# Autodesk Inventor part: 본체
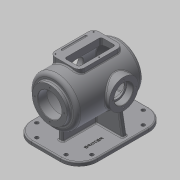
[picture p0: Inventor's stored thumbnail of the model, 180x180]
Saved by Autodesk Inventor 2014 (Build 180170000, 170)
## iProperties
Created: 2016-02
Part Number: 본체
Material: 일반
Document SubType Name: Modeling
Designer: mduedu
Density: 2.71 g/cm^3
Appearance: 기본값
Author: mduedu
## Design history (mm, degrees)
sketch "스케치2"
  geometry: L1 (0, 100)-(0, -100); L2 (65, -75.993)-(65, 100); L3 (65, 100)-(0, 100); A1 r 100 centre (0, 0) between (0, -100) and (65, -75.993); 2 further points
  constraints: 6 end point, 2 midpoint, 2 point on circle, 1 centre point, 1 coincident, 1 horizontal, 1 parallel, 1 vertical
  dimensions: "d3" = 200 distance of L1.start L1.end; "d5" = 130 diameter of L2 L1; "d6" = 100 radius of A1
revolve "회전1" sketch "스케치2" stored, may be unused: angle "d7" = 90 deg
sketch "스케치3"
  geometry: C1 r 47.5 at (0, 0); 1 further point
  constraints: 1 centre point, 1 coincident
  dimensions: "d8" = 95 diameter of C1
extrude "돌출2" join sketch "스케치3" distance "d10" = 10; taper "d11" = 0 deg
sketch "스케치5"
  geometry: L1 (47.5, 110)-(47.5, 100) reference; L2 (47.5, 100)-(65, 100) reference; L3 (65, 100)-(65, -75.993) reference; L4 (-65, -75.993)-(-65, 100) reference; L5 (-65, 100)-(-47.5, 100) reference; L6 (-47.5, 100)-(-47.5, 110) reference; L7 (-47.5, 110)-(47.5, 110) reference; L8 (55, 85)-(55, -71.239); L9 (0, 85)-(55, 85); L10 (0, 85)-(0, -90); A1 r 100 centre (0, 0) between (0, -100) and (65, -75.993) reference; A2 r 100 centre (0, 0) between (-65, -75.993) and (0, -100) reference; A3 r 90 centre (0, 0) between (0, -90) and (55, -71.239); 1 further point
  constraints: 6 end point, 2 point on circle, 1 centre point, 1 parallel, 1 perpendicular, 1 point on line, 1 vertical
  dimensions: "d13" = 10 distance between parallel lines of L3 L8; "d14" = 10 radial gap between concentric circles of A3 A1; "d15" = 15 distance between parallel lines of L9 L2
revolve "회전2" sketch "스케치5" stored, may be unused: angle "d16" = 90 deg
hole "구멍1" diameter "d19" = 65; stored, may be unused: countersink angle "d23" = 90 deg, drill point angle "d25" = 118 deg; dims "d17" = 10, "d18" = 10, "d20" = 6, "d21" = 4, "d22" = 2, "d24" = 8
node "작업 평면1"
sketch "스케치6"
  geometry: L1 (47.5, 110)-(-47.5, 110) reference; C1 r 40 at (0, -17); 1 further point
  constraints: 1 centre point, 1 vertical alignment
  dimensions: "d27" = 80 diameter of C1; "d29" = 127 distance from line of C1.centre L1
extrude "돌출3" join sketch "스케치6" stored distance "d30" = 10; taper "d31" = 0 deg
hole "구멍2" diameter "d34" = 42; stored, may be unused: countersink angle "d38" = 90 deg, drill point angle "d40" = 118 deg; dims "d32" = 10, "d33" = 10, "d35" = 6, "d36" = 52, "d37" = 18, "d39" = 8
sketch "스케치7" dims "d41" = 65
  geometry: C1 r 40 at (0, 0) reference; 3 further points
  constraints: 2 vertical alignment, 1 coincident, 2 other
hole "구멍3" sketch "스케치7" at (0, 32.5) diameter "d43" = 3.242; stored, may be unused: countersink angle "d47" = 90 deg, drill point angle "d49" = 118 deg; dims "d44" = 11, "d45" = 13, "d46" = 18, "d48" = 13
sketch "스케치8" dims "d53" = 80
  geometry: 3 further points
  constraints: 2 vertical alignment, 1 coincident, 2 other
hole "구멍4" sketch "스케치8" at (0, 40) diameter "d56" = 3.242; stored, may be unused: countersink angle "d60" = 90 deg, drill point angle "d62" = 118 deg; dims "d57" = 11, "d58" = 13, "d59" = 18, "d61" = 13
fillet "모깎기1" dims "d66" = 10
fillet "모깎기2" dims "d67" = 3
fillet "모깎기3" dims "d68" = 0.3
chamfer "모따기1" distance "d69" = 1; stored, may be unused: second distance "d70" = 2, angle "d71" = 45 deg
node "작업 평면5"
sketch "스케치23"
  geometry: L1 (6, 80)-(-6, 80); L2 (-6, 80)-(-6, -60); L3 (-6, -60)-(6, -60); L4 (6, -60)-(6, 80); L5 (-55, 100)-(55, 100) reference; 2 further points
  constraints: 8 end point, 2 parallel, 1 horizontal, 1 midpoint, 1 perpendicular, 1 vertical alignment
  dimensions: "d177" = 12 distance of L1.start L1.end; "d179" = 140 distance of L3.end L1.start; "d180" = 20 distance between parallel lines of L1 L5
extrude "돌출14" join sketch "스케치23" stored distance "d181" = 10; taper "d182" = 0 deg
node "작업 평면6"
sketch "스케치15"
  geometry: L1 (-30, 60)-(50, 60); L2 (50, 60)-(50, -60); L3 (50, -60)-(-30, -60); L4 (-30, -60)-(-30, 60); 3 further points
  constraints: 8 end point, 2 parallel, 1 horizontal, 1 horizontal alignment, 1 midpoint, 1 perpendicular, 1 vertical alignment
  dimensions: "d110" = 80 distance of L2.end L3.end; "d112" = 60 distance from line of L3 point (10, 0); "d113" = 120 distance of L1.end L2.end; "d149" = 30 distance from line of L4 point (0, 0)
extrude "돌출8" join sketch "스케치15" stored distance "d114" = 10; taper "d115" = 0 deg
fillet "모깎기7" dims "d116" = 15
sketch "스케치16"
  geometry: L1 (-30, -45)-(-30, 45) reference; L2 (-15, 60)-(35, 60) reference; L3 (35, -60)-(-15, -60) reference; L4 (-20, -45)-(-20, 45); L5 (-15, 50)-(15, 50); L6 (20, 45)-(20, -45); L7 (15, -50)-(-15, -50); L8 (50, 45)-(50, -45) reference; A1 r 15 centre (-15, -45) between (-30, -45) and (-15, -60) reference; A2 r 15 centre (-15, 45) between (-15, 60) and (-30, 45) reference; A3 r 5 centre (-15, -45) between (-20, -45) and (-15, -50); A4 r 5 centre (-15, 45) between (-15, 50) and (-20, 45); A5 r 5 centre (15, 45) between (20, 45) and (15, 50); A6 r 5 centre (15, -45) between (15, -50) and (20, -45); A7 r 15 centre (35, 45) between (50, 45) and (35, 60) reference; A8 r 15 centre (35, -45) between (35, -60) and (50, -45) reference
  constraints: 8 end point, 8 point on circle, 4 centre point, 2 equal radius, 3 other
  dimensions: "d137" = 10 distance between parallel lines of L4 L1; "d150" = 40 distance between parallel lines of L6 L4; "d151" = 100 distance between parallel lines of L7 L5
extrude "돌출9" cut sketch "스케치16" stored distance "d118" = 10; taper "d119" = 0 deg
fillet "모깎기8" dims "d120" = 3
sketch "스케치17"
  geometry: L1 (-30, -45)-(-30, 45) reference; L2 (-20, 45)-(-20, -45) reference; L3 (-15, -50)-(15, -50) reference; L4 (20, -45)-(20, 45) reference; L5 (15, 50)-(-15, 50) reference; L6 (-15, 60)-(35, 60) reference; L7 (35, -60)-(-15, -60) reference; L8 (15, 55)-(-15, 55); L9 (-25, 45)-(-25, -45); L10 (-15, -55)-(15, -55); L11 (25, -45)-(25, 45); L12 (50, 45)-(50, -45) reference; L13 (35, 55)-(-15, 55); L14 (-25, 45)-(-25, -45); L15 (-15, -55)-(35, -55); L16 (45, -45)-(45, 45); A1 r 5 centre (-15, 45) between (-15, 50) and (-20, 45) reference; A2 r 5 centre (-15, -45) between (-20, -45) and (-15, -50) reference; A3 r 5 centre (15, -45) between (15, -50) and (20, -45) reference; A4 r 5 centre (15, 45) between (20, 45) and (15, 50) reference; A5 r 15 centre (-15, 45) between (-15, 60) and (-30, 45) reference; A6 r 15 centre (-15, -45) between (-30, -45) and (-15, -60) reference; A7 r 10 centre (-15, 45) between (-15, 55) and (-25, 45); A8 r 10 centre (-15, -45) between (-25, -45) and (-15, -55); A9 r 10 centre (15, -45) between (15, -55) and (25, -45); A10 r 10 centre (15, 45) between (25, 45) and (15, 55); A11 r 15 centre (35, 45) between (50, 45) and (35, 60) reference; A12 r 15 centre (35, -45) between (35, -60) and (50, -45) reference; A13 r 10 centre (-15, 45) between (-15, 55) and (-25, 45); A14 r 10 centre (-15, -45) between (-25, -45) and (-15, -55); A15 r 10 centre (35, -45) between (35, -55) and (45, -45); A16 r 10 centre (35, 45) between (45, 45) and (35, 55); 6 further points
  constraints: 18 point on circle, 16 end point, 8 centre point, 4 midpoint, 4 tangent, 11 other
  dimensions: "d138" = 5 distance between parallel lines of L8 L6; "d157" = 5 distance between parallel lines of L12 L16
hole "구멍5" sketch "스케치17" at (-25, 0), (42.071, 52.071), (42.071, -52.071) diameter "d122" = 3.242; stored, may be unused: countersink angle "d126" = 90 deg, drill point angle "d128" = 118 deg; dims "d123" = 9, "d124" = 13, "d125" = 18, "d127" = 11
sketch "스케치19"
  geometry: L1 (-50, 70)-(-35, 70) reference; L2 (-50, 42.603)-(-50, 70) reference; C1 r 2.5 at (-43, 70); 1 further point
  constraints: 1 centre point, 1 point on line
  dimensions: "d152" = 5 diameter of C1; "d153" = 7 distance from line of C1.centre L2
extrude "돌출11" cut sketch "스케치19" stored distance "d154" = 70; taper "d155" = 0 deg
fillet "모깎기11" dims "d156" = 2.5
sketch "스케치20"
  geometry: L1 (-90, 120)-(90, 120); L2 (90, 120)-(90, -120); L3 (90, -120)-(-90, -120); L4 (-90, -120)-(-90, 120); 3 further points
  constraints: 8 end point, 2 parallel, 2 vertical alignment, 1 coincident, 1 horizontal, 1 midpoint, 1 perpendicular
  dimensions: "d162" = 180 distance of L1.start L1.end; "d164" = 240 distance of L1.end L2.end; "d165" = 120 distance from line of L1 point (0, 0)
extrude "돌출12" join sketch "스케치20" distance "d166" = 10; taper "d167" = 0 deg
fillet "모깎기12" dims "d168" = 50
node "작업 평면8"
  node "작업축1"
sketch "스케치24"
  geometry: L1 (128, 34.121)-(127.026, 32.5) reference; L2 (127.026, 32.5)-(128, 30.879) reference; L3 (128, 30.879)-(141, 30.879) reference; L4 (141, 30.879)-(141, 27) reference; L5 (141, 27)-(140, 26) reference; L6 (140, 26)-(123.3, 26) reference; L7 (123, 25.7)-(123, 21) reference; L8 (123, 21)-(116.833, 21) reference; L9 (86, 51.235)-(86, 70) reference; L10 (86, 70)-(106.5, 70) reference; L11 (111.5, 70)-(116, 70) reference; L12 (116, 70)-(116, 42.603) reference; L13 (118.678, 40)-(141, 40) reference; L14 (141, 40)-(141, 34.121) reference; L15 (141, 34.121)-(128, 34.121) reference; L16 (4, -34.121)-(4.974, -32.5) reference; L17 (4.974, -32.5)-(4, -30.879) reference; L18 (4, -30.879)-(-9, -30.879) reference; L19 (-9, -30.879)-(-9, -27) reference; L20 (-9, -27)-(-8, -26) reference; L21 (-8, -26)-(8.7, -26) reference; L22 (9, -25.7)-(9, -21) reference; L23 (9, -21)-(15.167, -21) reference; L24 (116.833, -21)-(123, -21) reference; L25 (123, -21)-(123, -25.7) reference; L26 (123.3, -26)-(140, -26) reference; L27 (140, -26)-(141, -27) reference; L28 (141, -27)-(141, -30.879) reference; L29 (141, -30.879)-(128, -30.879) reference; L30 (128, -30.879)-(127.026, -32.5) reference; L31 (127.026, -32.5)-(128, -34.121) reference; L32 (128, -34.121)-(141, -34.121) reference; L33 (141, -34.121)-(141, -40) reference; L34 (141, -40)-(118.678, -40) reference; L35 (72, -64.722)-(72, -100) reference; L36 (72, -100)-(156, -100) reference; L37 (156, -100)-(156, -110) reference; L38 (156, -110)-(-24, -110) reference; L39 (-24, -110)-(-24, -100) reference; L40 (-24, -100)-(60, -100) reference; L41 (60, -100)-(60, -64.722) reference; L42 (13.322, -40)-(-9, -40) reference; L43 (-9, -40)-(-9, -34.121) reference; L44 (-9, -34.121)-(4, -34.121) reference; L45 (4.974, 32.5)-(4, 34.121) reference; L46 (4, 34.121)-(-9, 34.121) reference; L47 (-9, 34.121)-(-9, 40) reference; L48 (-9, 40)-(13.322, 40) reference; L49 (36, 59.456)-(36, 70) reference; L50 (36, 70)-(46, 70) reference; L51 (46, 70)-(46, 51.235) reference; L52 (15.167, 21)-(9, 21) reference; L53 (9, 21)-(9, 25.7) reference; L54 (8.7, 26)-(-8, 26) reference; L55 (-8, 26)-(-9, 27) reference; L56 (-9, 27)-(-9, 30.879) reference; L57 (-9, 30.879)-(4, 30.879) reference; L58 (4, 30.879)-(4.974, 32.5) reference; L59 (-1, -40)-(-11.58, -100); A1 r 0.3 centre (123.3, 25.7) between (123.3, 26) and (123, 25.7) reference; A2 r 55 centre (66, 0) between (116.833, 21) and (86, 51.235) reference; A3 r 2.5 centre (109, 70) between (106.5, 70) and (111.5, 70) reference; A4 r 3 centre (119, 42.603) between (116, 42.603) and (116.516, 40.92) reference; A5 r 0.3 centre (8.7, -25.7) between (8.7, -26) and (9, -25.7) reference; A6 r 55 centre (66, 0) between (15.167, -21) and (116.833, -21) reference; A7 r 0.3 centre (123.3, -25.7) between (123, -25.7) and (123.3, -26) reference; A8 r 65 centre (66, 0) between (72, -64.722) and (116.354, -41.103) reference; A9 r 65 centre (66, 0) between (15.646, -41.103) and (60, -64.722) reference; A10 r 65 centre (66, 0) between (34.456, 56.833) and (15.646, 41.103) reference; A11 r 3 centre (33, 59.456) between (34.456, 56.833) and (36, 59.456) reference; A12 r 55 centre (66, 0) between (46, 51.235) and (15.167, 21) reference; A13 r 0.3 centre (8.7, 25.7) between (9, 25.7) and (8.7, 26) reference; 1 further point
  constraints: 2 end point, 2 point on line, 4 other
  dimensions: "d184" = 8 distance of L59.start L42.end; "d185" = 100 deg angle of L59 L40
feature "리브2" sketch "스케치24" dims "d186" = 1, "d187" = 12, "d188" = 0, "d189" = 0, "d190" = 1, "d191" = 1
fillet "모깎기15" dims "d192" = 3
fillet "모깎기16" dims "d193" = 3
sketch "스케치25"
  geometry: L1 (90, -70)-(90, 70) reference; L2 (40, 120)-(-40, 120) reference; L3 (-90, 70)-(-90, -70) reference; L4 (-40, -120)-(40, -120) reference; L5 (-74.004, 8)-(-9, 8) reference; L6 (-80.097, 20)-(-80.097, 14) reference; L7 (-9, 26)-(-74.004, 26) reference; L8 (-9, 57)-(-9, 26) reference; L9 (3, 63)-(-3, 63) reference; L10 (9, 26)-(9, 57) reference; L11 (74.004, 26)-(9, 26) reference; L12 (80.097, 14)-(80.097, 20) reference; L13 (9, 8)-(74.004, 8) reference; L14 (9, -77)-(9, 8) reference; L15 (-3, -83)-(3, -83) reference; L16 (-9, 8)-(-9, -77) reference; L17 (-40, 105)-(40, 105); L18 (75, 70)-(75, -70); L19 (40, -105)-(-40, -105); L20 (-75, -70)-(-75, 70); C1 r 5 at (-75, 70); C2 r 5 at (-40, 105); C3 r 5 at (40, 105); C4 r 5 at (75, 70); C5 r 5 at (75, -70); C6 r 5 at (40, -105); C7 r 5 at (-40, -105); C8 r 5 at (-75, -70); A1 r 50 centre (40, 70) between (90, 70) and (40, 120) reference; A2 r 50 centre (-40, 70) between (-40, 120) and (-90, 70) reference; A3 r 50 centre (-40, -70) between (-90, -70) and (-40, -120) reference; A4 r 50 centre (40, -70) between (40, -120) and (90, -70) reference; A5 r 6 centre (-3, 57) between (-3, 63) and (-9, 57) reference; A6 r 6 centre (3, 57) between (9, 57) and (3, 63) reference; A7 r 6 centre (3, -77) between (3, -83) and (9, -77) reference; A8 r 6 centre (-3, -77) between (-9, -77) and (-3, -83) reference; A9 r 35 centre (40, 70) between (75, 70) and (40, 105); A10 r 35 centre (40, -70) between (40, -105) and (75, -70); A11 r 35 centre (-40, -70) between (-75, -70) and (-40, -105); A12 r 35 centre (-40, 70) between (-40, 105) and (-75, 70); 5 further points; 4 other entities
  constraints: 12 centre point, 8 coincident, 8 end point, 8 point on circle, 7 equal radius, 11 other
  dimensions: "d194" = 15 distance between parallel lines of L17 L2; "d195" = 10 diameter of C1
extrude "돌출15" cut sketch "스케치25" stored distance "d197" = 10; taper "d198" = 0 deg
fillet "모깎기14" dims "d170" = 3
sketch "스케치22"
  geometry: L1 (90, -70)-(90, 70) reference; 2 further points
  constraints: 1 other
  dimensions: "d174" = 40 distance from line of L1 point (50, -40); "d199" = 40 vertical distance of point (50, -40) point (0, 0)
feature "엠보싱2" sketch "스케치22" dims "d13" = 10, "d175" = 0.5, "d176" = 0
node "솔리드2"
pattern_circular "원형 패턴1" dims angle "d51" = 360 deg
mirror "대칭1"
pattern_circular "원형 패턴2" dims angle "d64" = 360 deg
mirror "대칭3"
node "투영된 루프2"
node "절단 모서리 투영1"
node "절단 모서리 투영2"
node "절단 모서리 투영3"
node "절단 모서리 투영4"
other parameters: "d26" = 75, "d183" = 0
